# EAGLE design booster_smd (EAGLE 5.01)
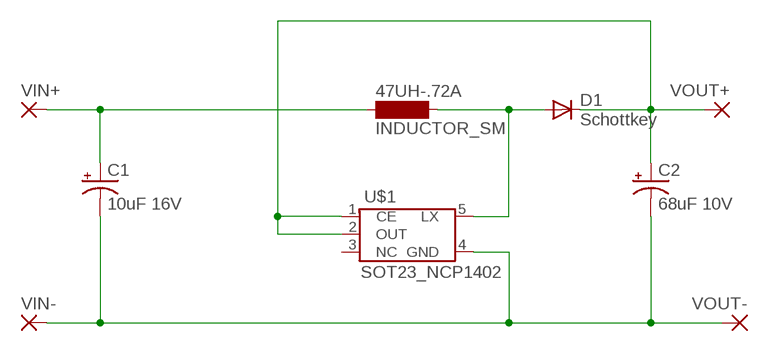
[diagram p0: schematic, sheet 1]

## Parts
47UH-.72A  INDUCTOR_SM  [INDUCTOR_SM]
C1  10uF 16V  CPOL-USC/6032-28R  [C/6032-28R]
C2  68uF 10V  CPOL-USC/6032-28R  [C/6032-28R]
D1  Schottkey  DIODE-SOD123  [SOD123]
U$1  SOT23_NCP1402  [SOT-23-5]
VIN+  SMD5  [SMD2,54-5,08]
VIN-  SMD5  [SMD2,54-5,08]
VOUT+  SMD5  [SMD2,54-5,08]
VOUT-  SMD5  [SMD2,54-5,08]

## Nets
N$1: 47UH-.72A.1 C1.+ VIN+.1(P)
N$2: 47UH-.72A.2 D1.A U$1.5(LX)
N$3: C2.+ D1.C U$1.1(CE) U$1.2(OUT) VOUT+.1(P)
N$4: C1.- C2.- U$1.4(GND) VIN-.1(P) VOUT-.1(P)
Unconnected: U$1.3(NC)

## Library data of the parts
47UH-.72A = 1dmf:INDUCTOR_SM
C1 C2 = rcl:CPOL-US: POLARIZED CAPACITOR, American symbol
D1 = diode:DIODE-: DIODE
U$1 = 1dmf:SOT23_NCP1402
VIN+ VIN- VOUT+ VOUT- = wirepad:SMD5: SMD PAD

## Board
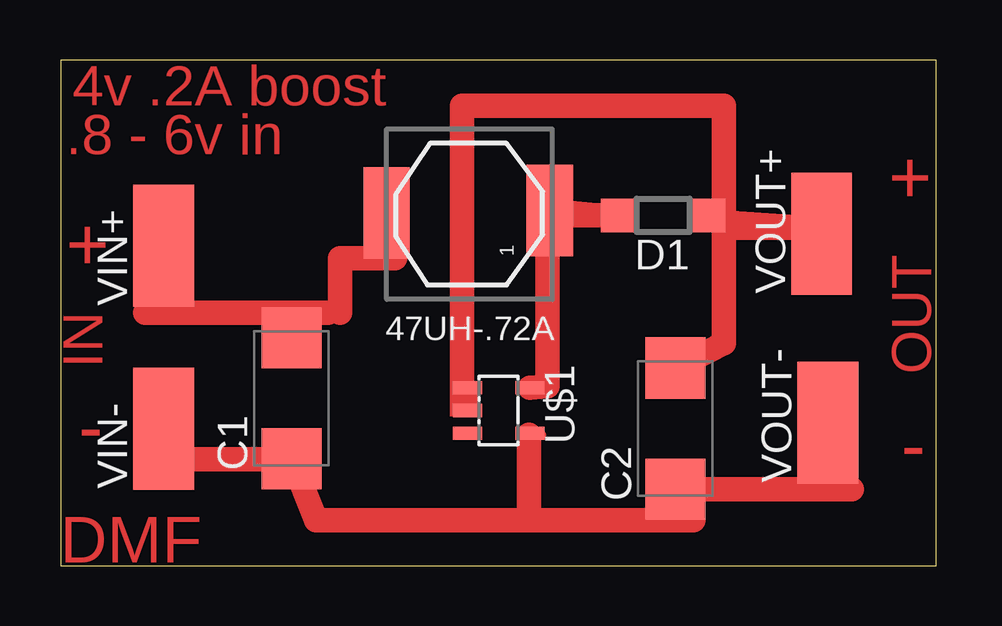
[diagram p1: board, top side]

Size 36.5 x 21.07 mm. Coordinates in mm from the lower left corner, seen from the top.
Outline: 0,0 36.5,0 36.5,21.07 0,21.07 0,0
Copper layers (1*16): Top 0.035mm / dielectric 1.5mm / Bottom 0.035mm
Design rules "default": minimum track width 10mil, minimum drill 24mil, track to track 8mil, track to pad 8mil, pad to pad 8mil, via to via 8mil, smd to smd 8mil, copper to edge 40mil, drill to drill 8mil, minimum pad ring 10mil, minimum via ring 8mil, stop-mask expansion 4mil, vias tented up to drill 0mil, thermal gap 10mil

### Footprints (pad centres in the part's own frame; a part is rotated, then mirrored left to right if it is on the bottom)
INDUCTOR_SM = smd 3.81 x 1.93: 1 0.1,3.4; 2 0.2,-3.4
C/6032-28R = smd 2.55 x 2.5: + 2.525,0; - -2.525,0
SOD123 = smd 1.4 x 1.4: A 1.9,0; C -1.9,0
SOT-23-5 = smd 0.55 x 1.2: 1 -0.95,-1.3; 2 0,-1.3; 3 0.95,-1.3; 4 0.95,1.3; 5 -0.95,1.3
SMD2,54-5,08 = smd 2.54 x 5.08: 1 0,0

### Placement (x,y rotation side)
47UH-.72A  16.98,14.6 90 top
C1  9.61,6.98 90 top
C2  25.62,5.71 90 top
D1  25.11,14.6 180 top
U$1  18.25,6.47 270 top
VIN+  4.28,13.33 0 top
VIN-  4.28,5.71 0 top
VOUT+  31.71,13.84 0 top
VOUT-  31.97,5.96 0 top

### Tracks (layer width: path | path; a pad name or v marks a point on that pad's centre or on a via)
N$1
  Top 0.254: 3.52,10.54 5.3,11.04 VIN+.1 | 11.14,10.54 C1.+ 11.65,10.54 | 13.93,12.82 47UH-.72A.1
  Top 1.016: 3.52,10.54 11.14,10.54 | 13.93,12.82 11.65,12.82 11.65,10.54
N$2
  Top 0.254: 21.81,14.6 47UH-.72A.2
  Top 1.016: 22.31,14.6 21.81,14.6 20.28,14.6 20.28,7.49 U$1.5 | 22.31,14.6 D1.A | 47UH-.72A.2 22.31,14.6
N$3
  Top 0.254: 16.73,12.06 U$1.1 | 27.65,14.09 D1.C 31.97,14.29 27.9,14.09 | U$1.2 16.98,6.73 | 26.12,8.25 C2.+ | 31.46,14.09 VOUT+.1
  Top 0.406: 16.73,6.73 16.98,6.73 | 31.97,14.29 32.22,14.29 27.65,14.6
  Top 1.016: 27.65,14.09 27.65,9.27 C2.+ | 27.9,14.09 31.46,14.09 | 16.73,6.73 16.73,12.06 16.73,19.17 27.65,19.17 27.65,14.6
N$4
  Top 0.254: C1.- | 5.3,4.44 VIN-.1
  Top 0.406: 32.22,3.42 32.98,3.19 31.97,4.69 VOUT-.1 | 19.52,5.46 20.03,5.46 | 26.38,1.9 C2.- | U$1.4 19.52,3.74
  Top 1.016: 5.3,4.44 C1.- | C1.- 10.63,1.9 19.52,1.9 | C2.- 32.98,3.19 | 19.52,1.9 26.38,1.9 | 19.52,1.9 19.52,3.74 19.52,5.46
(copper drawn outside any net)
  shapes: Top area x1

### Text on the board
Top: 4v .2A boost | .8 - 6v in | + | + | IN | OUT | - | - | DMF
